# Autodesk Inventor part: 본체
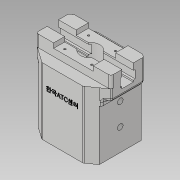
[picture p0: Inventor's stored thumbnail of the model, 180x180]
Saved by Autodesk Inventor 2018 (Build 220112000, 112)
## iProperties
Created: 2023-05
Part Number: 본체
Material: 일반
Document SubType Name: Modeling
Designer: home
Density: 1 g/cm^3
Appearance: 기본값
Author: home
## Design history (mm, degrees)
sketch "스케치1"
  geometry: L1 (-40, -35)-(40, -35); L2 (40, -35)-(40, 35); L3 (40, 35)-(-40, 35); L4 (-40, 35)-(-40, -35); L5 (-40, -35)-(40, 35); L6 (40, -35)-(-40, 35); 1 further point
  constraints: 12 end point, 2 midpoint, 2 parallel, 1 horizontal, 1 perpendicular
  dimensions: "d0" = 80 distance of L3.end L2.end; "d1" = 70 distance of L2.end L1.end
extrude "돌출1" new body sketch "스케치1" distance "d2" = 70; taper "d3" = 0 deg
sketch "스케치2"
  geometry: L1 (-40, -35)-(-40, 35) reference; L2 (-40, 35)-(40, 35) reference; L3 (40, 35)-(40, -35) reference; L4 (40, -35)-(-40, -35) reference; L5 (-40, -35)-(40, -35) reference; L6 (-26, -35)-(-47.241, -20); L7 (-47.241, 20)-(-26, 35); L8 (-47.241, 20)-(-47.241, -20); L9 (-26, 35)-(26, 35); L10 (-26, -35)-(26, -35); L11 (47.241, 20)-(26, 35); L12 (47.241, 20)-(47.241, -20); L13 (26, -35)-(47.241, -20); L14 (-26, -35)-(26, -35); 1 further point
  constraints: 18 end point, 2 parallel, 1 collinear
extrude "돌출2" join sketch "스케치2" distance "d10" = 29; taper "d11" = 0 deg
sketch "스케치3"
  geometry: L1 (0.814, 99)-(0.814, 78); L2 (-21.186, 99)-(-21.186, 84); L3 (22.814, 99)-(22.814, 84); L4 (-35, 70)-(-35, 99) reference; L5 (-35, 84)-(-35, 99); L6 (35, 99)-(22.814, 99); L7 (35, 99)-(20, 99) reference; L8 (35, 99)-(35, 84); L9 (35, 70)-(35, 99) reference; L10 (-35, 84)-(-21.186, 84); L11 (-20, 99)-(-35, 99) reference; L12 (22.814, 84)-(35, 84); 2 further points
  constraints: 16 end point, 2 collinear, 2 parallel, 2 perpendicular, 1 point on line, 1 vertical
  dimensions: "d12" = 21 distance of L1.start L1.end; "d13" = 22 distance between parallel lines of L1 L2; "d14" = 22 distance between parallel lines of L1 L3; "d17" = 15 distance between parallel lines of L11 L10
extrude "돌출3" cut sketch "스케치3" extent not by distance; stored distance "d15" = 29; taper "d16" = 0 deg
sketch "스케치4"
  geometry: L1 (-21.186, 84)-(-21.186, 99) reference; L2 (-21.186, 99)-(22.814, 99) reference; L3 (22.814, 99)-(22.814, 84) reference; L4 (22.814, 84)-(35, 84) reference; L5 (35, 84)-(35, 0) reference; L6 (35, 0)-(-35, 0) reference; L7 (-35, 0)-(-35, 84) reference; L8 (-35, 84)-(-21.186, 84) reference; L9 (20, 99)-(-20, 99) reference; L10 (-7.2, 78)-(7.2, 78); L11 (-9, 99)-(9, 99); L12 (9.368, 80.581)-(9.368, 90.419); L13 (7.2, 91)-(9.368, 90.419); L14 (7.2, 80)-(9.368, 80.581); L15 (9.368, 80)-(10.883, 80); L16 (-7.2, 91)-(-9.368, 90.419); L17 (-9.368, 80.581)-(-9.368, 90.419); L18 (-7.2, 80)-(-9.368, 80.581); L19 (-7.2, 99)-(-7.2, 91); L20 (-7.2, 80)-(-7.2, 78); L21 (7.2, 99)-(7.2, 91); L22 (7.2, 80)-(7.2, 78); L23 (-7.2, 99)-(7.2, 99); 1 further point
  constraints: 28 end point, 3 horizontal, 1 point on line
  dimensions: "d30" = 15 deg angle of L15 L14
extrude "돌출4" cut sketch "스케치4" extent not by distance; stored distance "d31" = 29; taper "d32" = 0 deg
sketch "스케치5"
  geometry: C1 r 30 at (0, 0); 1 further point
  constraints: 1 centre point, 1 coincident
  dimensions: "d33" = 60 diameter of C1
extrude "돌출5" cut sketch "스케치5" distance "d34" = 5.8; taper "d35" = 0 deg
hole "구멍1" diameter "d38" = 60; stored, may be unused: countersink angle "d42" = 90 deg, drill point angle "d44" = 0 deg; dims "d39" = 6, "d40" = 63, "d41" = 2.2, "d43" = 8.8, "d45" = 10, "d46" = 10
hole "구멍2" diameter "d49" = 50; stored, may be unused: countersink angle "d53" = 110 deg, drill point angle "d55" = 0 deg; dims "d50" = 6, "d51" = 52, "d52" = 2.2, "d54" = 45, "d103" = 10, "d104" = 10
chamfer "모따기1" distance "d58" = 1; stored, may be unused: second distance "d59" = 2, angle "d60" = 45 deg
sketch "스케치6"
  geometry: L1 (40, -35)-(-40, -35) reference; L2 (-40, -35)-(-40, 35) reference; L3 (-40, 35)-(40, 35) reference; L4 (40, 35)-(40, -35) reference; L5 (-43.256, 22.814)-(-47.241, 20) reference; L6 (-47.241, 20)-(-24.231, 36.249); L7 (-47.241, 20)-(-47.241, 36.249); L8 (-47.241, 36.249)-(-24.231, 36.249); L9 (47.305, 20)-(24.131, 36.249); L10 (24.131, 36.249)-(47.305, 36.249); L11 (40, 35)-(-40, 35) reference; L12 (47.305, 20)-(47.305, 36.249); C1 r 31 at (0, 0) reference; 1 further point
  constraints: 12 end point, 2 perpendicular, 1 collinear, 1 parallel, 1 vertical
extrude "돌출6" cut sketch "스케치6" extent not by distance; stored distance "d61" = 5.8; taper "d62" = 0 deg
fillet "모깎기1" dims "d63" = 3
fillet "모깎기2" dims "d64" = 3
sketch "스케치7"
  geometry: L1 (5.563, -29)-(0, -29) reference; L2 (0, -29)-(0, -15) reference; L3 (0, -15)-(91.125, -15) reference; L4 (91.125, 0)-(91.125, -15) reference; L5 (0, 0)-(91.125, 0) reference; L6 (0, -15)-(0, 0) reference; L7 (5.563, -99)-(5.563, -29) reference; L8 (22.931, -99)-(5.563, -99) reference; L9 (24.322, -93.2)-(24.322, -98) reference; L10 (22.251, -93.2)-(24.322, -93.2) reference; L11 (22.251, -91)-(22.251, -93.2) reference; L12 (24.322, -91)-(22.251, -91) reference; L13 (24.322, -84.4)-(24.322, -91) reference; L14 (32.29, -39.4)-(32.29, -83.7) reference; L15 (58.835, -39.4)-(32.29, -39.4) reference; L16 (58.835, -83.7)-(58.835, -39.4) reference; L17 (66.803, -91)-(66.803, -84.4) reference; L18 (68.874, -91)-(66.803, -91) reference; L19 (68.874, -93.2)-(68.874, -91) reference; L20 (66.803, -93.2)-(68.874, -93.2) reference; L21 (66.803, -98)-(66.803, -93.2) reference; L22 (85.563, -99)-(68.194, -99) reference; L23 (85.563, -29)-(85.563, -99) reference; L24 (91.125, -29)-(85.563, -29) reference; L25 (91.125, -15)-(91.125, -29) reference; L26 (92.804, 0)-(-1.679, 0) reference; L27 (70.563, 0)-(70.563, -6); L28 (20.563, 0)-(20.563, -6); L29 (20.563, -6)-(70.563, -6); L30 (20.563, 0)-(70.563, 0); L31 (30.49, -84.4)-(24.322, -84.4) reference; L32 (66.803, -84.4)-(60.635, -84.4) reference; 1 further point
  constraints: 8 end point, 1 collinear, 1 horizontal, 4 other
extrude "돌출7" cut sketch "스케치7" extent not by distance; stored distance "d70" = 5.8; taper "d71" = 0 deg
sketch "스케치8"
  geometry: L1 (47.241, 70)-(40, 70) reference; L2 (40, 70)-(40, 0) reference; L3 (40, 0)-(31, 0) reference; L4 (31, 0)-(30, 1) reference; L5 (30, 1)-(30, 5.8) reference; L6 (30, 5.8)-(31.5, 5.8) reference; L7 (31.5, 5.8)-(31.5, 8) reference; L8 (31.5, 8)-(30, 8) reference; L9 (30, 8)-(30, 14.6) reference; L10 (26, 14.6)-(25, 15.3) reference; L11 (25, 15.3)-(25, 59.6) reference; L12 (25, 59.6)-(-25, 59.6) reference; L13 (-25, 59.6)-(-25, 15.3) reference; L14 (-25, 15.3)-(-26, 14.6) reference; L15 (-30, 14.6)-(-30, 8) reference; L16 (-30, 8)-(-31.5, 8) reference; L17 (-31.5, 8)-(-31.5, 5.8) reference; L18 (-31.5, 5.8)-(-30, 5.8) reference; L19 (-30, 5.8)-(-30, 1) reference; L20 (-30, 1)-(-31, 0) reference; L21 (-31, 0)-(-40, 0) reference; L22 (-40, 0)-(-40, 70) reference; L23 (-40, 70)-(-47.241, 70) reference; L24 (-47.241, 70)-(-47.241, 78) reference; L25 (-47.241, 78)-(47.241, 78) reference; L26 (47.241, 78)-(47.241, 70) reference; L27 (-40, 0)-(-38, 0); L28 (-26.688, 0)-(-40, 0) reference; L29 (-38, 0)-(-38, 64); L30 (-40, 0)-(-40, 64); L31 (-38, 64)-(-40, 64); L32 (30, 14.6)-(26, 14.6) reference; L33 (-26, 14.6)-(-30, 14.6) reference; 1 further point
  constraints: 8 end point, 2 perpendicular, 1 collinear, 1 point on line
  dimensions: "d72" = 2 distance of L21.end L27.end; "d73" = 64 distance from line of L27.end L31
extrude "돌출8" cut sketch "스케치8" extent not by distance; stored distance "d74" = 5.8; taper "d75" = 0 deg
sketch "스케치9"
  geometry: L1 (-78, 19.324)-(-78, 33.724) reference; L2 (-78, 33.724)-(-80, 33.724) reference; L3 (-80, 33.724)-(-80.581, 35.892) reference; L4 (-80.581, 35.892)-(-90.419, 35.892) reference; L5 (-90.419, 35.892)-(-91, 33.724) reference; L6 (-91, 33.724)-(-99, 33.724) reference; L7 (-99, 33.724)-(-99, 49.339) reference; L8 (-99, 49.339)-(-84, 49.339) reference; L9 (-84, 49.339)-(-84, 53.049) reference; L10 (-84, 53.049)-(-64, 53.049) reference; L11 (-64, 53.049)-(-64, 0) reference; L12 (0, 0)-(-64, 0) reference; L13 (0, 53.049)-(0, 0) reference; L14 (-64, 53.049)-(0, 53.049) reference; L15 (-80, 19.324)-(-78, 19.324) reference; L16 (-80.581, 17.156)-(-80, 19.324) reference; L17 (-90.419, 17.156)-(-80.581, 17.156) reference; L18 (-91, 19.324)-(-90.419, 17.156) reference; L19 (-99, 19.324)-(-91, 19.324) reference; L20 (-99, 5.339)-(-99, 19.324) reference; L21 (-84, 5.339)-(-99, 5.339) reference; L22 (-84, 0)-(-84, 5.339) reference; L23 (-64, 0)-(-84, 0) reference; L24 (0, 26.524)-(-28, 26.524); L25 (-28, 26.524)-(-56, 26.524)
  constraints: 4 end point, 2 horizontal
  dimensions: "d76" = 28 distance of L24.start L24.end; "d84" = 28 distance of L24.end L25.end
hole "구멍4" sketch "스케치9" at (-56, 26.524), (-28, 26.524) diameter "d85" = 7.134; stored, may be unused: countersink angle "d89" = 110 deg, drill point angle "d91" = 118 deg; dims "d86" = 7, "d87" = 60, "d88" = 2.2, "d90" = 11
sketch "스케치10"
  geometry: L1 (0, -14.4)-(0, -28.386) reference; L2 (50, -28.386)-(0, -28.386) reference; L3 (70.563, -28.386)-(50, -28.386) reference; L4 (72.241, -27.2)-(70.563, -28.386) reference; L5 (72.241, -14.4)-(72.241, -27.2) reference; L6 (50, -14.4)-(72.241, -14.4) reference; L7 (50, -28.386)-(50, -14.4) reference; L8 (0, -14.4)-(50, -14.4) reference; L9 (-22.241, -14.4)-(0, -14.4) reference; L10 (-22.241, -27.2)-(-22.241, -14.4) reference; L11 (-20.563, -28.386)-(-22.241, -27.2) reference; L12 (0, -28.386)-(-20.563, -28.386) reference; L13 (50, 0)-(50, 15.614) reference; L14 (0, 15.614)-(50, 15.614) reference; L15 (-18.256, 15.614)-(0, 15.614) reference; L16 (-22.241, 12.8)-(-18.256, 15.614) reference; L17 (-22.241, 0)-(-22.241, 12.8) reference; L18 (0, 0)-(-22.241, 0) reference; L19 (0, 15.614)-(0, 0) reference; L20 (50, 0)-(0, 0) reference; L21 (72.241, 0)-(50, 0) reference; L22 (72.241, 12.8)-(72.241, 0) reference; L23 (68.256, 15.614)-(72.241, 12.8) reference; L24 (50, 15.614)-(68.256, 15.614) reference; C1 r 12 at (25, -7.2); 1 further point
  constraints: 1 centre point, 1 coincident
  dimensions: "d92" = 12 radius of C1
extrude "돌출9" cut sketch "스케치10" extent not by distance; stored distance "d93" = 5.8; taper "d94" = 0 deg
sketch "스케치12"
  geometry: L1 (72.207, -27.8)-(22.194, -27.8) reference; L2 (20.463, -27.251)-(0, -12.8) reference; L3 (0, -12.8)-(0, 0) reference; L4 (0, 0)-(37.641, 0) reference; L5 (94.483, 14.4)-(56.841, 14.4) reference; L6 (94.483, 27.2)-(94.483, 14.4) reference; L7 (85.561, 33.5)-(94.483, 27.2) reference; L8 (73.929, 41.656)-(85.561, 33.5) reference; L9 (22.194, 42.2)-(72.207, 42.2) reference; L10 (0, 27.2)-(20.463, 41.651) reference; L11 (0, 14.4)-(0, 27.2) reference; L12 (0, 0)-(0, 14.4) reference; L13 (85.561, -19.1)-(73.929, -27.256) reference; L14 (94.483, -12.8)-(85.561, -19.1) reference; L15 (94.483, 0)-(94.483, -12.8) reference; L16 (56.841, 0)-(94.483, 0) reference; L17 (94.483, 14.4)-(94.483, 0) reference; L18 (37.641, 14.4)-(0, 14.4) reference; L19 (18.241, 13.2)-(76.241, 13.2); L20 (18.241, 1.2)-(76.241, 1.2); A1 r 12 centre (47.241, 7.2) between (37.641, 14.4) and (37.641, 0) reference; A2 r 3 centre (72.207, -24.8) between (72.207, -27.8) and (73.929, -27.256) reference; A3 r 3 centre (22.194, -24.8) between (20.463, -27.251) and (22.194, -27.8) reference; A4 r 12 centre (47.241, 7.2) between (37.641, 0) and (56.841, 0) reference; A5 r 12 centre (47.241, 7.2) between (56.841, 0) and (56.841, 14.4) reference; A6 r 3 centre (72.207, 39.2) between (73.929, 41.656) and (72.207, 42.2) reference; A7 r 3 centre (22.194, 39.2) between (22.194, 42.2) and (20.463, 41.651) reference; A8 r 12 centre (47.241, 7.2) between (37.641, 14.4) and (37.641, 0) reference; A9 r 12 centre (47.241, 7.2) between (56.841, 14.4) and (37.641, 14.4) reference; A10 r 6 centre (18.241, 7.2) between (18.241, 13.2) and (18.241, 1.2); A11 r 6 centre (76.241, 7.2) between (76.241, 1.2) and (76.241, 13.2); 1 further point
  constraints: 4 end point, 4 point on circle, 2 centre point, 1 coincident, 1 tangent
extrude "돌출10" cut sketch "스케치12" distance "d101" = 9; taper "d102" = 0 deg
sketch "스케치13"
  geometry: 1 further point
fillet "모깎기3" dims "d105" = 2
sketch "스케치14"
  geometry: L1 (72.241, -15.614)-(50, -15.614) reference; L2 (50, -15.614)-(34.6, -15.614) reference; L3 (15.4, -15.614)-(0, -15.614) reference; L4 (0, -15.614)-(-22.241, -15.614) reference; L5 (-22.241, -15.614)-(-22.241, -2.814) reference; L6 (-22.241, -2.814)-(-18.256, 0) reference; L7 (-18.256, 0)-(0, 0) reference; L8 (0, 0)-(0, -15.614) reference; L9 (72.241, -2.814)-(72.241, -15.614) reference; L10 (68.256, 0)-(72.241, -2.814) reference; L11 (50, 0)-(68.256, 0) reference; L12 (50, -15.614)-(50, 0) reference; L13 (0, 0)-(50, 0) reference; L14 (0, -30.014)-(0, -44) reference; L15 (50, -44)-(0, -44) reference; L16 (70.563, -44)-(50, -44) reference; L17 (72.241, -42.814)-(70.563, -44) reference; L18 (72.241, -30.014)-(72.241, -42.814) reference; L19 (50, -30.014)-(72.241, -30.014) reference; L20 (34.6, -30.014)-(50, -30.014) reference; L21 (0, -30.014)-(15.4, -30.014) reference; L22 (-22.241, -30.014)-(0, -30.014) reference; L23 (-22.241, -42.814)-(-22.241, -30.014) reference; L24 (-20.563, -44)-(-22.241, -42.814) reference; L25 (0, -44)-(-20.563, -44) reference; L26 (50, -44)-(50, -30.014) reference; L27 (8, -37.814)-(42, -37.814); L28 (42, -37.814)-(42, -7.814); L29 (42, -7.814)-(8, -7.814); L30 (8, -7.814)-(8, -37.814); L31 (8, -37.814)-(42, -7.814); L32 (42, -37.814)-(8, -7.814); A1 r 12 centre (25, -22.814) between (34.6, -15.614) and (15.4, -15.614) reference; A2 r 12 centre (25, -22.814) between (15.4, -30.014) and (34.6, -30.014) reference
  constraints: 12 end point, 2 midpoint, 2 parallel, 1 horizontal, 1 perpendicular
  dimensions: "d106" = 34 distance of L29.end L28.end; "d107" = 30 distance of L28.end L27.end
hole "구멍5" sketch "스케치14" at (8, -7.814), (42, -7.814), (8, -37.814), (42, -37.814) diameter "d108" = 2.459; stored, may be unused: countersink angle "d112" = 110 deg, drill point angle "d114" = 118 deg; dims "d109" = 6, "d110" = 60, "d111" = 2.2, "d113" = 8
sketch "스케치15"
  geometry: L1 (-26, 25)-(26, 25); L2 (26, 25)-(26, -25); L3 (26, -25)-(-26, -25); L4 (-26, -25)-(-26, 25); L5 (-26, 25)-(26, -25); L6 (26, 25)-(-26, -25); C1 r 31 at (0, 0) reference
  constraints: 12 end point, 2 midpoint, 2 parallel, 1 horizontal, 1 perpendicular
  dimensions: "d115" = 52 distance of L2.end L3.end; "d116" = 50 distance of L1.end L2.end
hole "구멍6" sketch "스케치15" at (-26, 25), (26, 25), (26, -25), (-26, -25) diameter "d117" = 4.917; stored, may be unused: countersink angle "d121" = 110 deg, drill point angle "d123" = 118 deg; dims "d118" = 12, "d119" = 60, "d120" = 2.2, "d122" = 14
sketch "스케치17"
  geometry: L1 (-20.515, 99)-(0.048, 99) reference; L2 (-14.952, 0)-(-14.952, 70) reference; 2 further points
  constraints: 1 other
  dimensions: "d125" = 40 distance from line of L1 point (25.048, 59); "d126" = 40 distance from line of L2 point (25.048, 59)
feature "엠보싱1" sketch "스케치17" dims "d0" = 80, "d1" = 70, "d127" = 0.5, "d128" = 0
fillet "모깎기4" dims "d129" = 3
fillet "모깎기6" dims "d131" = 3
fillet "모깎기8" dims "d133" = 3
fillet "모깎기9" dims "d134" = 3
node "솔리드1"
mirror "미러1"
node "절단 모서리 투영1"
node "절단 모서리 투영2"
node "절단 모서리 투영3"
node "절단 모서리 투영4"
node "절단 모서리 투영5"
node "절단 모서리 투영6"
node "절단 모서리 투영7"
node "절단 모서리 투영9"
node "절단 모서리 투영10"
other parameters: "d24" = 7.2, "d25" = 7.2
